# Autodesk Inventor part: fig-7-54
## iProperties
Shininess: 77.0
Length Units: 11269
Angle Units: 11279
Time Units: 11290
Mass Units: 11283
Length Display Precision: 3
Angle Display Precision: 2
Created: 2002-01
Part Number: fig-7-54
Document SubType Name: Modeling
Designer: ***
Density: 1 g/cm^3
Density: 0.0
Volumn: 0.0
Area: 0.0
PropertySet Name: Model Information
Control State: 0
Master: False
Checked Out: False
Author: ***
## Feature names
1. Extrusion1
